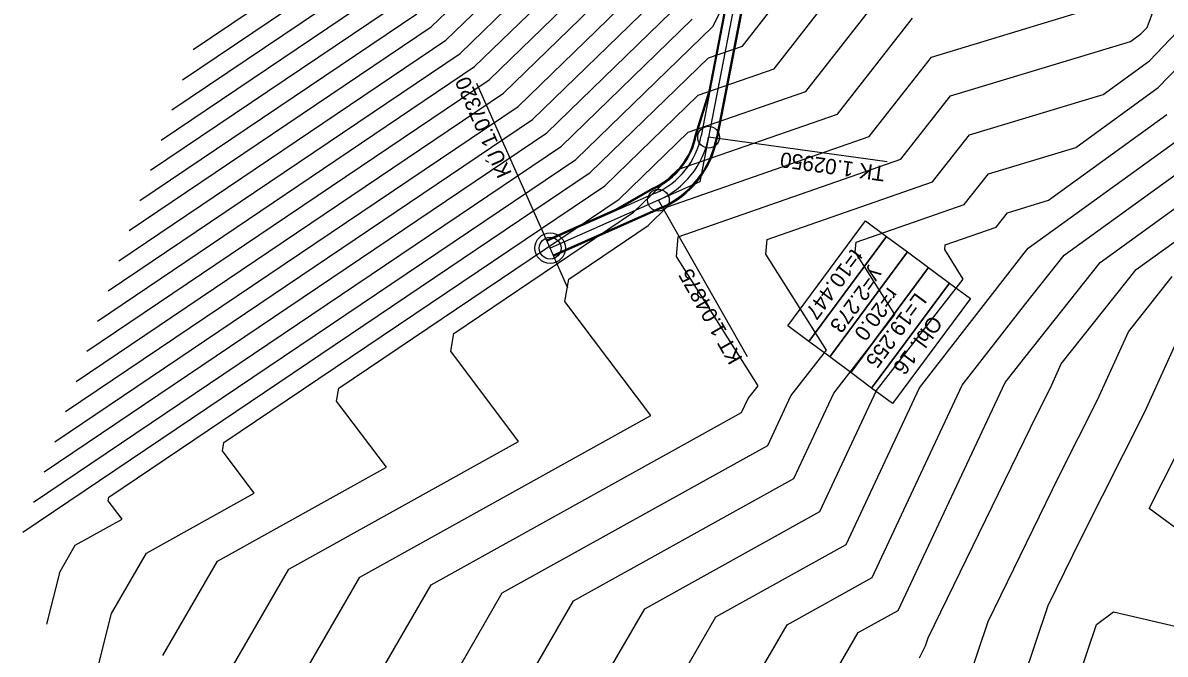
# Model space of a CAD drawing. Extents: x -549394 to -546608, y -1037055 to -1033629.
# Drawn here: x -547351.1 to -547088.8, y -1036607.7 to -1036462.8 of the extents above; entities that cross this region are included whole.
import ezdxf

# ---------------------------------------------------------------- set-up
doc = ezdxf.new("R2010")
doc.units = 0
for name, color, linetype in [('hlavni_vrst', 7, 'Continuous'), ('norm_vrst', 7, 'Continuous'), ('POLYGONY_SITUACE_PO', 7, 'Continuous'), ('u_sirka_7m', 7, 'Continuous'), ('x_navrh_C31', 7, 'Continuous'), ('x_osa_C31', 7, 'Continuous'), ('x_popis_oblouky_C31', 7, 'Continuous'), ('x_popis_pricne_rezy_C31', 7, 'Continuous')]:
    doc.layers.add(name, color=color, linetype=linetype)

msp = doc.modelspace()

# ---------------------------------------------------------------- linework, layer by layer
at = {"layer": 'hlavni_vrst'}
for p, q in [((-547311.97, -1036468.9), (-547277.21, -1036445.47)), ((-547244.02, -1036475.86), (-547221.12, -1036453.65)), ((-547324.2, -1036503.52), (-547260.62, -1036460.67)), ((-547227.42, -1036491.06), (-547197.38, -1036461.91)), ((-547164, -1036483.69), (-547146.77, -1036461.68)), ((-547336.43, -1036538.14), (-547244.02, -1036475.86)), ((-547200.66, -1036496.43), (-547164, -1036483.69)), ((-547115.54, -1036503.49), (-547088.34, -1036483.8)), ((-547348.65, -1036572.75), (-547227.42, -1036491.06)), ((-547210.82, -1036506.25), (-547200.68, -1036496.41)), ((-547200.68, -1036496.41), (-547200.66, -1036496.43)), ((-547125, -1036506.36), (-547115.54, -1036503.49)), ((-547252.13, -1036534.09), (-547210.82, -1036506.25)), ((-547127.6, -1036509.68), (-547125, -1036506.36)), ((-547139.3, -1036513.75), (-547127.6, -1036509.68)), ((-547139.39, -1036514.79), (-547139.3, -1036513.75)), ((-547135.11, -1036521.57), (-547139.39, -1036514.79)), ((-547097.18, -1036533.65), (-547087.14, -1036521)), ((-547155.02, -1036547.17), (-547135.11, -1036521.57)), ((-547252.82, -1036538.16), (-547252.13, -1036534.09)), ((-547104.29, -1036549.32), (-547097.18, -1036533.65)), ((-547237.24, -1036558.82), (-547252.82, -1036538.16)), ((-547168.04, -1036574.9), (-547155.02, -1036547.17)), ((-547113.16, -1036566.88), (-547104.29, -1036549.32)), ((-547290.03, -1036588.14), (-547237.24, -1036558.82)), ((-547129.38, -1036600.2), (-547113.16, -1036566.88)), ((-547208.29, -1036597.26), (-547168.04, -1036574.9)), ((-547307.11, -1036617.61), (-547290.03, -1036588.14)), ((-547248.03, -1036665.8), (-547208.29, -1036597.26)), ((-547134, -1036613.83), (-547129.38, -1036600.2))]:
    msp.add_line(p, q, dxfattribs=at)
at = {"layer": 'norm_vrst'}
for p, q in [((-547257.3, -1036463.71), (-547240.11, -1036447.04)), ((-547178.55, -1036473.29), (-547157.64, -1036446.58)), ((-547314.42, -1036475.82), (-547273.89, -1036448.51)), ((-547253.98, -1036466.75), (-547235.36, -1036448.69)), ((-547250.66, -1036469.78), (-547230.62, -1036450.34)), ((-547316.86, -1036482.75), (-547270.57, -1036451.55)), ((-547247.34, -1036472.82), (-547225.87, -1036451.99)), ((-547171.27, -1036478.49), (-547151.12, -1036452.75)), ((-547319.31, -1036489.67), (-547267.25, -1036454.59)), ((-547240.7, -1036478.9), (-547216.37, -1036455.3)), ((-547321.76, -1036496.59), (-547263.93, -1036457.63)), ((-547237.38, -1036481.94), (-547211.62, -1036456.95)), ((-547185.83, -1036468.09), (-547176.48, -1036456.14)), ((-547234.06, -1036484.98), (-547206.88, -1036458.61)), ((-547230.74, -1036488.02), (-547202.13, -1036460.26)), ((-547192.63, -1036463.57), (-547191.06, -1036460.49)), ((-547142.41, -1036470.62), (-547106.86, -1036459.85)), ((-547092.92, -1036463.83), (-547091.33, -1036459.67)), ((-547326.65, -1036510.44), (-547257.3, -1036463.71)), ((-547224.1, -1036494.1), (-547192.63, -1036463.57)), ((-547096.73, -1036467.03), (-547094.33, -1036465.3)), ((-547094.33, -1036465.3), (-547092.92, -1036463.83)), ((-547092.33, -1036471.47), (-547086.06, -1036464.92)), ((-547090.34, -1036477.64), (-547079.2, -1036466.02)), ((-547329.09, -1036517.36), (-547253.98, -1036466.75)), ((-547193.63, -1036470.8), (-547185.83, -1036468.09)), ((-547138.06, -1036479.55), (-547096.73, -1036467.03)), ((-547331.54, -1036524.29), (-547250.66, -1036469.78)), ((-547220.78, -1036497.13), (-547193.63, -1036470.8)), ((-547193.63, -1036470.8), (-547193.63, -1036470.8)), ((-547156.72, -1036488.89), (-547142.41, -1036470.62)), ((-547333.98, -1036531.21), (-547247.34, -1036472.82)), ((-547195.97, -1036479.34), (-547178.55, -1036473.29)), ((-547103, -1036479.19), (-547092.33, -1036471.47)), ((-547338.87, -1036545.06), (-547240.7, -1036478.9)), ((-547198.32, -1036487.89), (-547171.27, -1036478.49)), ((-547133.7, -1036488.49), (-547103, -1036479.19)), ((-547109.27, -1036491.34), (-547090.34, -1036477.64)), ((-547217.46, -1036500.17), (-547195.98, -1036479.33)), ((-547195.98, -1036479.33), (-547195.97, -1036479.34)), ((-547149.44, -1036494.09), (-547138.06, -1036479.55)), ((-547341.32, -1036551.98), (-547237.38, -1036481.94)), ((-547343.76, -1036558.91), (-547234.06, -1036484.98)), ((-547346.21, -1036565.83), (-547230.74, -1036488.02)), ((-547214.14, -1036503.21), (-547198.33, -1036487.87)), ((-547203.01, -1036504.97), (-547156.72, -1036488.89)), ((-547198.33, -1036487.87), (-547198.32, -1036487.89)), ((-547142.16, -1036499.28), (-547133.7, -1036488.49)), ((-547129.35, -1036497.42), (-547109.27, -1036491.34)), ((-547120.21, -1036514.49), (-547086.34, -1036489.97)), ((-547351.1, -1036579.68), (-547224.1, -1036494.1)), ((-547200.57, -1036511.85), (-547149.44, -1036494.09)), ((-547331.33, -1036571.63), (-547220.78, -1036497.13)), ((-547134.88, -1036504.48), (-547129.35, -1036497.42)), ((-547111.94, -1036516.12), (-547084.35, -1036496.14)), ((-547304.93, -1036559.12), (-547217.46, -1036500.17)), ((-547180.15, -1036512.48), (-547142.16, -1036499.28)), ((-547103.67, -1036517.74), (-547082.35, -1036502.31)), ((-547278.53, -1036546.61), (-547214.14, -1036503.21)), ((-547207.5, -1036509.29), (-547203.02, -1036504.95)), ((-547203.02, -1036504.95), (-547203.01, -1036504.97)), ((-547159.72, -1036513.12), (-547134.88, -1036504.48)), ((-547225.74, -1036521.58), (-547207.5, -1036509.29)), ((-547095.4, -1036519.37), (-547080.35, -1036508.48)), ((-547200.96, -1036516.39), (-547200.57, -1036511.85)), ((-547180.43, -1036515.85), (-547180.15, -1036512.48)), ((-547159.91, -1036515.32), (-547159.72, -1036513.12)), ((-547166.54, -1036537.89), (-547180.43, -1036515.85)), ((-547150.82, -1036529.73), (-547159.91, -1036515.32)), ((-547145.18, -1036546.56), (-547121.11, -1036515.63)), ((-547121.11, -1036515.63), (-547120.21, -1036514.49)), ((-547182.25, -1036546.05), (-547200.96, -1036516.39)), ((-547121.06, -1036527.59), (-547111.94, -1036516.12)), ((-547121, -1036539.56), (-547103.67, -1036517.74)), ((-547112.63, -1036541.06), (-547095.4, -1036519.37)), ((-547226.61, -1036526.73), (-547225.74, -1036521.58)), ((-547093.46, -1036552.08), (-547081.74, -1036526.24)), ((-547206.89, -1036552.86), (-547226.61, -1036526.73)), ((-547135.34, -1036545.95), (-547121.06, -1036527.59)), ((-547164.86, -1036547.78), (-547150.82, -1036529.73)), ((-547174.7, -1036548.38), (-547166.54, -1036537.89)), ((-547125.5, -1036545.34), (-547121, -1036539.56)), ((-547115.12, -1036546.55), (-547112.63, -1036541.06)), ((-547279.04, -1036549.6), (-547278.53, -1036546.61)), ((-547184.54, -1036548.99), (-547182.25, -1036546.05)), ((-547162.04, -1036582.47), (-547145.18, -1036546.56)), ((-547156.04, -1036590.04), (-547135.34, -1036545.95)), ((-547150.04, -1036597.61), (-547125.5, -1036545.34)), ((-547118.23, -1036552.71), (-547115.12, -1036546.55)), ((-547267.59, -1036564.77), (-547279.04, -1036549.6)), ((-547186.04, -1036552.18), (-547184.54, -1036548.99)), ((-547180.04, -1036559.75), (-547174.7, -1036548.38)), ((-547174.04, -1036567.33), (-547164.86, -1036547.78)), ((-547257.33, -1036591.79), (-547186.04, -1036552.18)), ((-547108.08, -1036581.05), (-547093.46, -1036552.08)), ((-547273.68, -1036589.97), (-547206.89, -1036552.86)), ((-547143.18, -1036603.94), (-547118.23, -1036552.71)), ((-547092.42, -1036574.24), (-547082.64, -1036554.84)), ((-547305.26, -1036561.03), (-547304.93, -1036559.12)), ((-547240.99, -1036593.61), (-547180.04, -1036559.75)), ((-547297.94, -1036570.73), (-547305.26, -1036561.03)), ((-547306.38, -1036586.32), (-547267.59, -1036564.77)), ((-547224.64, -1036595.44), (-547174.04, -1036567.33)), ((-547322.72, -1036584.5), (-547297.94, -1036570.73)), ((-547331.47, -1036572.47), (-547331.33, -1036571.63)), ((-547328.29, -1036576.68), (-547331.47, -1036572.47)), ((-547064.45, -1036594.95), (-547092.42, -1036574.24)), ((-547339.07, -1036582.67), (-547328.29, -1036576.68)), ((-547115.59, -1036596.46), (-547108.08, -1036581.05)), ((-547342.56, -1036588.69), (-547339.07, -1036582.67)), ((-547191.94, -1036599.08), (-547162.04, -1036582.47)), ((-547330.74, -1036598.33), (-547322.72, -1036584.5)), ((-547318.93, -1036607.97), (-547306.38, -1036586.32)), ((-547345.58, -1036600.75), (-547342.56, -1036588.69)), ((-547295.29, -1036627.25), (-547273.68, -1036589.97)), ((-547283.48, -1036636.89), (-547257.33, -1036591.79)), ((-547175.6, -1036600.9), (-547156.04, -1036590.04)), ((-547271.66, -1036646.53), (-547240.99, -1036593.61)), ((-547259.84, -1036656.17), (-547224.64, -1036595.44)), ((-547124.36, -1036622.38), (-547115.59, -1036596.46)), ((-547337.68, -1036626.05), (-547330.74, -1036598.33)), ((-547236.21, -1036675.44), (-547191.94, -1036599.08)), ((-547159.25, -1036602.73), (-547150.04, -1036597.61)), ((-547104.53, -1036600.82), (-547100.6, -1036597.93)), ((-547100.6, -1036597.93), (-547060.05, -1036607.35)), ((-547224.39, -1036685.08), (-547175.6, -1036600.9)), ((-547114.72, -1036630.92), (-547104.53, -1036600.82)), ((-547212.58, -1036694.72), (-547159.25, -1036602.73)), ((-547143.64, -1036605.29), (-547143.18, -1036603.94)), ((-547145.21, -1036608.53), (-547143.8, -1036605.76)), ((-547143.8, -1036605.76), (-547143.64, -1036605.31)), ((-547143.64, -1036605.31), (-547143.64, -1036605.29))]:
    msp.add_line(p, q, dxfattribs=at)
at = {"layer": 'POLYGONY_SITUACE_PO'}
for centre in [(-547193.6, -1036489.01), (-547205.14, -1036503.49), (-547229.99, -1036514.48)]:
    msp.add_circle(centre, 2.5, dxfattribs=at)
at = {"layer": 'u_sirka_7m'}
msp.add_circle((-547229.99, -1036514.48), 3.5, dxfattribs=at)
at = {"layer": 'x_navrh_C31'}
for p, q in [((-547166.72, -1036341.14), (-547195.32, -1036488.67)), ((-547163.28, -1036341.8), (-547191.88, -1036489.34)), ((-547196.62, -1036488.41), (-547193.66, -1036478.8)), ((-547196.38, -1036488.47), (-547193.42, -1036478.86)), ((-547205.85, -1036501.89), (-547230.7, -1036512.88)), ((-547206.4, -1036500.68), (-547215.11, -1036505.71)), ((-547206.29, -1036500.9), (-547215, -1036505.94)), ((-547204.43, -1036505.09), (-547229.28, -1036516.08)), ((-547204.33, -1036505.32), (-547229.18, -1036516.31)), ((-547215.11, -1036505.71), (-547230.8, -1036512.65))]:
    msp.add_line(p, q, dxfattribs=at)
for points in [[(-547163.03, -1036341.85), (-547191.64, -1036489.39)], [(-547168.87, -1036350.92), (-547193.66, -1036478.8)]]:
    msp.add_lwpolyline(points, dxfattribs=at)
for radius, start, end in [(16.92, 293.8224, 349.0736), (17.17, 293.8678, 349.0282), (18.25, 293.8678, 349.0282), (21.75, 293.8678, 349.0282), (22, 293.8678, 349.0282)]:
    msp.add_arc((-547213.23, -1036485.2), radius, start, end, dxfattribs=at)
at = {"layer": 'x_osa_C31'}
for points in [[(-547007, -1036074.62), (-547209.87, -1036086.14), (-547207.44, -1036130.66), (-547193.81, -1036201.52), (-547173.1, -1036299.52), (-547166.67, -1036306.7), (-547163.9, -1036335.81), (-547195.59, -1036499.26)], [(-547195.59, -1036499.26), (-547229.99, -1036514.48)]]:
    msp.add_lwpolyline(points, dxfattribs=at)
msp.add_arc((-547213.23, -1036485.2), 20, 293.8678, 349.0282, dxfattribs=at)
at = {"layer": 'x_popis_oblouky_C31'}
for points in [[(-547229.99, -1036514.48), (-547246.82, -1036476.69)], [(-547152.62, -1036494.7), (-547193.6, -1036489.01)], [(-547184.69, -1036539.45), (-547205.14, -1036503.49)]]:
    msp.add_lwpolyline(points, dxfattribs=at)
for points in [[(-547152.76, -1036511.77), (-547170.62, -1036535.87), (-547175.44, -1036532.3), (-547157.58, -1036508.2)], [(-547147.94, -1036515.34), (-547165.8, -1036539.45), (-547170.62, -1036535.87), (-547152.76, -1036511.77)], [(-547143.12, -1036518.91), (-547160.98, -1036543.02), (-547165.8, -1036539.45), (-547147.94, -1036515.34)], [(-547138.3, -1036522.48), (-547156.16, -1036546.59), (-547160.98, -1036543.02), (-547143.12, -1036518.91)], [(-547133.48, -1036526.06), (-547151.34, -1036550.16), (-547156.16, -1036546.59), (-547138.3, -1036522.48)]]:
    msp.add_lwpolyline(points, close=True, dxfattribs=at)
at = {"layer": 'x_popis_pricne_rezy_C31'}
msp.add_lwpolyline([(-547225.94, -1036523.63), (-547229.99, -1036514.48), (-547234.03, -1036505.34)], dxfattribs=at)

# ---------------------------------------------------------------- texts
at = {"layer": 'x_popis_oblouky_C31'}
for s, rotation, p in [('KÚ 1.07320', 114.0075, (-547238.72, -1036497.33)), ('TK 1.02950', 172.0941, (-547152.91, -1036495.73)), ('t=10.447', 233.4888, (-547160.66, -1036514.37)), ('y=2.273', 233.4888, (-547155.97, -1036518.71)), ('KT 1.04875', 119.6287, (-547185.7, -1036539.82)), ('r=20.0', 233.4888, (-547152.4, -1036523.24)), ('L=19.255', 233.4888, (-547146.06, -1036524.46)), ('Obl. 16', 233.4888, (-547142.45, -1036529.67))]:
    msp.add_text(s, height=3.5, rotation=rotation, dxfattribs=at).set_placement(p)

doc.saveas('drawing.dxf')
